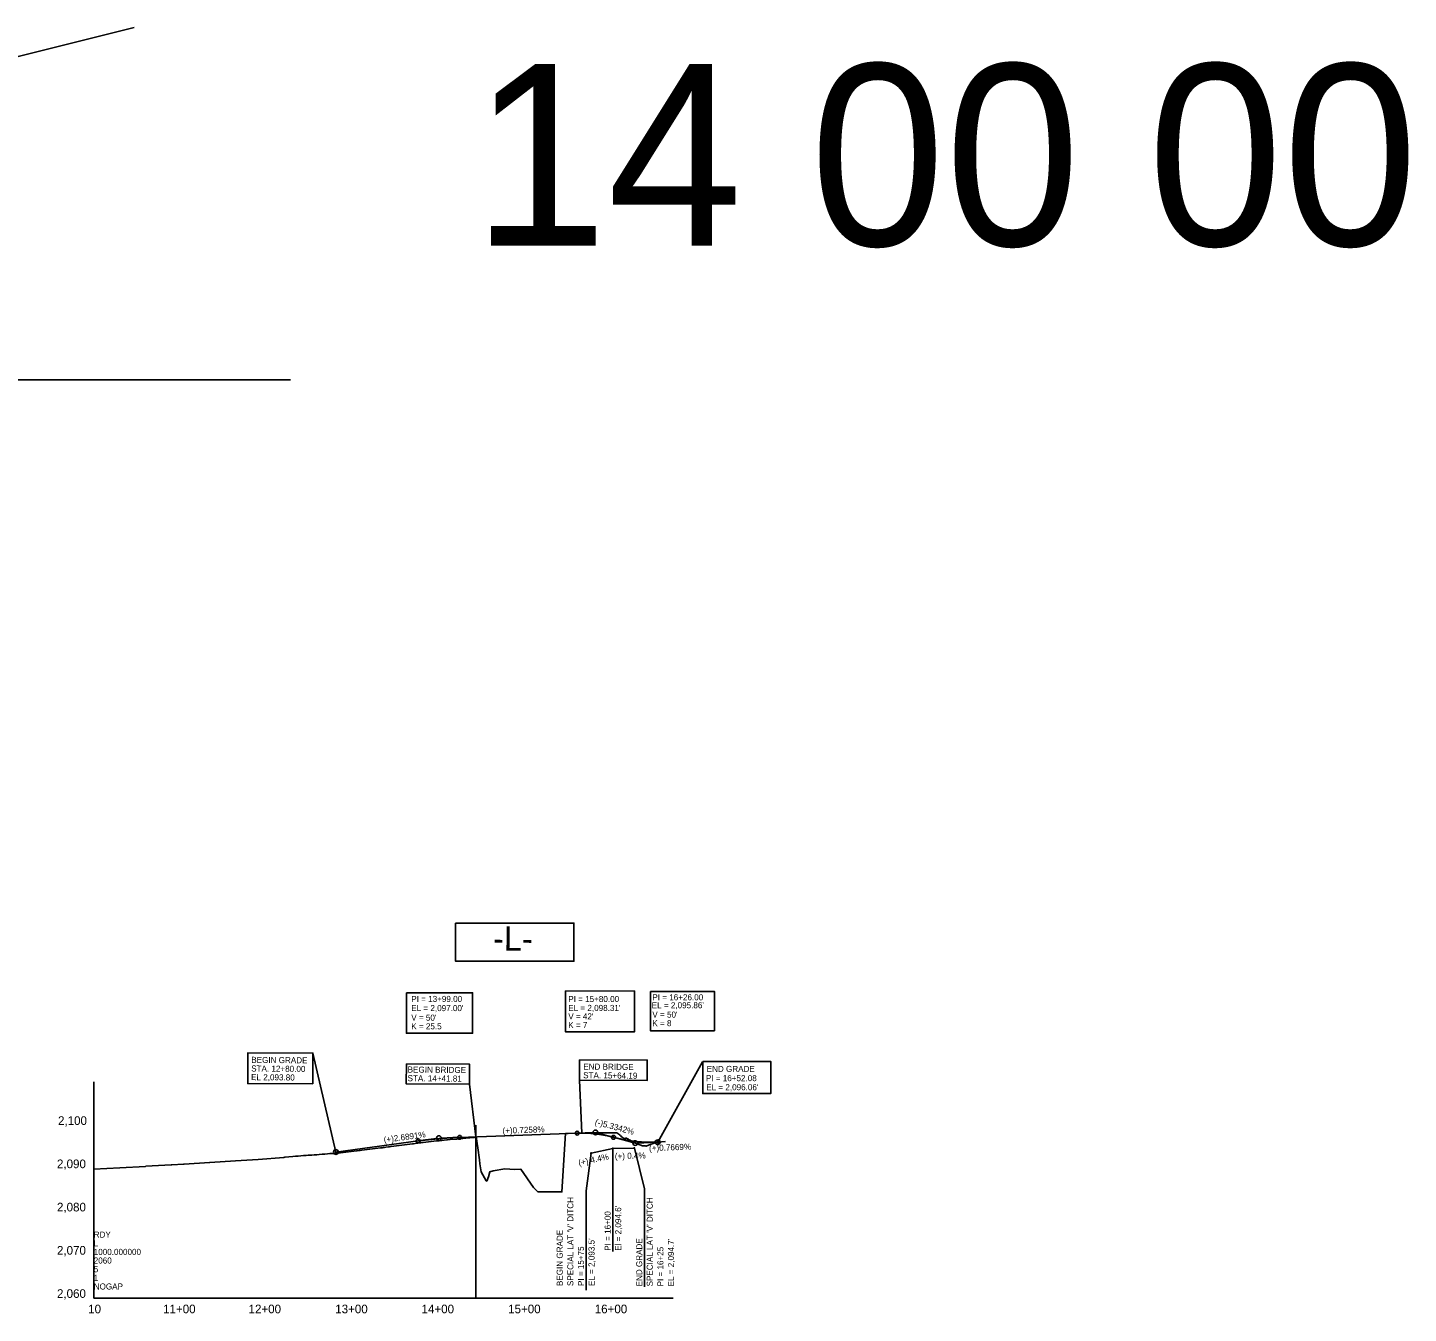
# Model space of a CAD drawing. Extents: x 1030663 to 1033857, y 654635 to 657099.
# Drawn here: x 1032261 to 1033857, y 654635 to 656121 of the extents above; entities that cross this region are included whole.
import ezdxf

# ---------------------------------------------------------------- set-up
doc = ezdxf.new("R2010")
doc.units = 0
for name, color, linetype in [('Exist Profile Cell', 7, 'Continuous'), ('Exist Vertical Profile Ground Line', 7, 'Continuous'), ('Exist Vertical Profile Horizontal Axis Label Major', 7, 'Continuous'), ('Exist Vertical Profile Vertical Axis Label', 7, 'Continuous'), ('Prop Grid Mask', 7, 'Continuous'), ('Prop Vertical Profile Curve Label', 7, 'Continuous'), ('Prop Vertical Profile Ditch Grade Right', 7, 'Continuous'), ('Prop Vertical Profile Ditch Grade Right Label', 7, 'Continuous'), ('Prop Vertical Profile Grade', 7, 'Continuous'), ('Prop Vertical Profile Grade Label', 7, 'Continuous'), ('Prop VPI Ditch Grade Right Label', 7, 'Continuous'), ('Prop VPI Label', 7, 'Continuous')]:
    doc.layers.add(name, color=color, linetype=linetype)

msp = doc.modelspace()

# ---------------------------------------------------------------- linework, layer by layer
at = {"layer": 'Exist Profile Cell'}
for q in [(1032337.1, 654902.3), (1033007.1, 654652.3), (1032337.1, 654652.3)]:
    msp.add_line((1032337.1, 654652.3), q, dxfattribs=at)
at = {"layer": 'Exist Vertical Profile Ground Line'}
msp.add_lwpolyline([(1032337.1, 654801.3), (1032367.2, 654803), (1032396.9, 654804.7), (1032397.3, 654804.8), (1032426.8, 654806.5), (1032427.3, 654806.5), (1032441, 654807.3), (1032441.5, 654807.4), (1032471, 654809.2), (1032471.3, 654809.2), (1032501.1, 654811.1), (1032527.1, 654812.7), (1032556.7, 654815.1), (1032558.2, 654815.3), (1032567.2, 654816.1), (1032570.3, 654816.3), (1032573.3, 654816.6), (1032576.4, 654816.8), (1032579.5, 654817.1), (1032582.6, 654817.3), (1032584.9, 654817.5), (1032585.6, 654817.6), (1032588.7, 654817.7), (1032589.1, 654817.7), (1032591.8, 654818), (1032594.9, 654818.2), (1032597.9, 654818.4), (1032601, 654818.7), (1032604.1, 654818.9), (1032607.2, 654819.2), (1032610.2, 654819.4), (1032611.2, 654819.5), (1032613.3, 654819.6), (1032615.5, 654819.7), (1032616.4, 654819.8), (1032619.5, 654820.1), (1032622.5, 654820.5), (1032625.6, 654820.9), (1032628.7, 654821.2), (1032631.8, 654821.6), (1032634.8, 654822), (1032637.9, 654822.4), (1032641, 654822.7), (1032641.6, 654822.8), (1032644.1, 654823.1), (1032645.1, 654823.2), (1032647.1, 654823.5), (1032650.2, 654823.8), (1032653.3, 654824.2), (1032656.4, 654824.6), (1032659.4, 654825), (1032662.5, 654825.3), (1032665.6, 654825.7), (1032668.6, 654826.1), (1032670.5, 654826.3), (1032671.7, 654826.5), (1032672.7, 654826.6), (1032673.1, 654826.6), (1032674.8, 654826.8), (1032677.9, 654827.2), (1032679.1, 654827.3), (1032680.4, 654827.5), (1032680.9, 654827.6), (1032684, 654827.9), (1032687.1, 654828.3), (1032690.2, 654828.7), (1032693.2, 654829.1), (1032696.3, 654829.5), (1032699.4, 654829.9), (1032702.5, 654830.3), (1032705.5, 654830.6), (1032706.9, 654830.8), (1032708.6, 654831), (1032711.7, 654831.4), (1032714.8, 654831.8), (1032715.4, 654831.9), (1032717.8, 654832.2), (1032720.9, 654832.6), (1032724, 654833), (1032727.1, 654833.4), (1032730.1, 654833.7), (1032733.2, 654834.1), (1032734.7, 654834.3), (1032736.3, 654834.4), (1032739.4, 654834.7), (1032742.4, 654835), (1032745.5, 654835.3), (1032746, 654835.4), (1032749, 654835.7), (1032756.7, 654836.2), (1032767.1, 654837.4), (1032776.9, 654837.9), (1032779.4, 654838.7), (1032781.1, 654826.3), (1032783.1, 654812.1), (1032783.6, 654807.7), (1032784.9, 654798.5), (1032790.8, 654788), (1032791.4, 654787.6), (1032793.3, 654792.4), (1032795.2, 654798.5), (1032798.8, 654799.5), (1032812.2, 654801.8), (1032824.1, 654801.1), (1032830.9, 654801.3), (1032845.5, 654780.1), (1032850.6, 654775.1), (1032861.2, 654775.1), (1032878.4, 654775.1), (1032882.6, 654842.6), (1032906.1, 654843.1), (1032912.5, 654843.3), (1032916.4, 654843.4), (1032917.5, 654843.4), (1032918.5, 654843.4), (1032919.5, 654843.4), (1032920.5, 654843.4), (1032921.5, 654843.4), (1032922.6, 654843.5), (1032923.6, 654843.5), (1032924.6, 654843.5), (1032925.6, 654843.5), (1032926.6, 654843.4), (1032927.7, 654843.4), (1032928.7, 654843.4), (1032929.7, 654843.4), (1032930.7, 654843.4), (1032931.7, 654843.4), (1032932.8, 654843.4), (1032933.8, 654843.4), (1032934.8, 654843.4), (1032935.8, 654843.4), (1032936.8, 654843.5), (1032937.9, 654843.5), (1032938.9, 654843.5), (1032939.2, 654843.5), (1032939.9, 654843.5), (1032940.9, 654843.5), (1032942, 654843.5), (1032943, 654842.7), (1032944, 654841.9), (1032945, 654841.1), (1032946, 654840.2), (1032947, 654839.3), (1032948.1, 654838.4), (1032949.1, 654837.5), (1032949.5, 654837), (1032950.1, 654837.1), (1032951.1, 654837.1), (1032952.1, 654837.2), (1032953.4, 654837.2), (1032954.2, 654836.7), (1032955.2, 654836.1), (1032956.2, 654835.4), (1032957.2, 654834.8), (1032958.3, 654834.1), (1032959.3, 654833.4), (1032960.3, 654832.7), (1032961.3, 654832.4), (1032962.3, 654832), (1032963.4, 654831.6), (1032964.4, 654831.3), (1032965.4, 654830.9), (1032966.4, 654830.5), (1032967.4, 654830.1), (1032968.5, 654829.7), (1032969.7, 654829.2), (1032970.5, 654828.8), (1032971.6, 654828.4), (1032972.5, 654828.3), (1032973.6, 654828.3), (1032974.6, 654828.3), (1032975.6, 654828.2), (1032976.2, 654828.2), (1032976.6, 654828.4), (1032977.6, 654828.8), (1032978.6, 654829.2), (1032979.7, 654829.6), (1032980.7, 654830), (1032981.7, 654830.3), (1032982.7, 654830.7), (1032983.7, 654831.1), (1032984.8, 654831.5), (1032986.2, 654832), (1032987.4, 654832.4), (1032987.9, 654832.6), (1032989.2, 654832.6), (1032997.9, 654833.4), (1032997.9, 654833.4)], dxfattribs=at)
at = {"layer": 'Prop Grid Mask'}
for points in [[(1032755.5, 655086), (1032892.2, 655086), (1032892.2, 655041.8), (1032755.5, 655041.8)], [(1032698.6, 655005.4), (1032775, 655005.4), (1032775, 654958.6), (1032698.6, 654958.6)], [(1032882.5, 655007.6), (1032962.3, 655007.4), (1032962.2, 654960.2), (1032882.4, 654960.4)], [(1033054.9, 654961.4), (1032980.7, 654961.5), (1032980.8, 655006.8), (1033054.9, 655006.7)], [(1032590.4, 654900.3), (1032515.2, 654900.5), (1032515.3, 654936), (1032590.5, 654935.7)], [(1032698.5, 654923.2), (1032771.4, 654923), (1032771.4, 654899.9), (1032698.4, 654900.1)], [(1032898.8, 654927.8), (1032977.1, 654927.6), (1032977.1, 654904.1), (1032898.8, 654904.2)], [(1033041.2, 654926.1), (1033119.8, 654926), (1033119.7, 654888.8), (1033041.1, 654888.9)]]:
    msp.add_lwpolyline(points, close=True, dxfattribs=at)
at = {"layer": 'Prop Vertical Profile Curve Label'}
for centre in [(1032760.1, 654838.2), (1032896.1, 654843.1), (1032938.1, 654838.3), (1032712.1, 654834.1), (1032988.1, 654832.6)]:
    msp.add_circle(centre, 2.25, dxfattribs=at)
at = {"layer": 'Prop Vertical Profile Ditch Grade Right'}
msp.add_lwpolyline([(1032912.1, 654819.8), (1032937.1, 654825.3), (1032962.1, 654825.8)], dxfattribs=at)
at = {"layer": 'Prop Vertical Profile Grade'}
for p, q in [((1032760.1, 654838.2), (1032896.1, 654843.1)), ((1032617.1, 654821.3), (1032712.1, 654834.1)), ((1032988.1, 654832.6), (1032989.2, 654832.6))]:
    msp.add_line(p, q, dxfattribs=at)
for points in [[(1032896.1, 654843.1), (1032897, 654843.2), (1032897.8, 654843.2), (1032898.7, 654843.2), (1032899.5, 654843.2), (1032900.3, 654843.2), (1032901.2, 654843.2), (1032902, 654843.2), (1032902.9, 654843.2), (1032903.7, 654843.2), (1032904.5, 654843.2), (1032905.4, 654843.2), (1032906.2, 654843.1), (1032907.1, 654843.1), (1032907.9, 654843.1), (1032908.7, 654843), (1032909.6, 654843), (1032910.4, 654842.9), (1032911.3, 654842.9), (1032912.1, 654842.8), (1032912.9, 654842.7), (1032913.8, 654842.7), (1032914.6, 654842.6), (1032915.5, 654842.5), (1032916.3, 654842.4), (1032917.1, 654842.3), (1032918, 654842.2), (1032918.8, 654842.1), (1032919.7, 654842), (1032920.5, 654841.9), (1032921.3, 654841.8), (1032922.2, 654841.6), (1032923, 654841.5), (1032923.9, 654841.4), (1032924.7, 654841.2), (1032925.5, 654841.1), (1032926.4, 654840.9), (1032927.2, 654840.8), (1032928.1, 654840.6), (1032928.9, 654840.5), (1032929.7, 654840.3), (1032930.6, 654840.1), (1032931.4, 654839.9), (1032932.3, 654839.7), (1032933.1, 654839.5), (1032933.9, 654839.4), (1032934.8, 654839.1), (1032935.6, 654838.9), (1032936.5, 654838.7), (1032937.3, 654838.5), (1032938.1, 654838.3)], [(1032712.1, 654834.1), (1032713.1, 654834.2), (1032714.1, 654834.4), (1032715, 654834.5), (1032716, 654834.6), (1032716.9, 654834.7), (1032717.9, 654834.8), (1032718.9, 654835), (1032719.8, 654835.1), (1032720.8, 654835.2), (1032721.7, 654835.3), (1032722.7, 654835.4), (1032723.7, 654835.5), (1032724.6, 654835.6), (1032725.6, 654835.7), (1032726.5, 654835.8), (1032727.5, 654835.9), (1032728.5, 654836), (1032729.4, 654836.1), (1032730.4, 654836.2), (1032731.3, 654836.3), (1032732.3, 654836.4), (1032733.3, 654836.5), (1032734.2, 654836.6), (1032735.2, 654836.7), (1032736.1, 654836.7), (1032737.1, 654836.8), (1032738.1, 654836.9), (1032739, 654837), (1032740, 654837.1), (1032740.9, 654837.1), (1032741.9, 654837.2), (1032742.9, 654837.3), (1032743.8, 654837.3), (1032744.8, 654837.4), (1032745.7, 654837.5), (1032746.7, 654837.5), (1032747.7, 654837.6), (1032748.6, 654837.6), (1032749.6, 654837.7), (1032750.5, 654837.8), (1032751.5, 654837.8), (1032752.5, 654837.9), (1032753.4, 654837.9), (1032754.4, 654838), (1032755.3, 654838), (1032756.3, 654838), (1032757.3, 654838.1), (1032758.2, 654838.1), (1032759.2, 654838.2), (1032760.1, 654838.2)], [(1032938.1, 654838.3), (1032939.1, 654838), (1032940.1, 654837.8), (1032941.1, 654837.5), (1032942.1, 654837.3), (1032943.1, 654837), (1032944.1, 654836.8), (1032945.1, 654836.6), (1032946.1, 654836.4), (1032947.1, 654836.1), (1032948.1, 654835.9), (1032949.1, 654835.7), (1032950.1, 654835.5), (1032951.1, 654835.3), (1032952.1, 654835.2), (1032953.1, 654835), (1032954.1, 654834.8), (1032955.1, 654834.6), (1032956.1, 654834.5), (1032957.1, 654834.3), (1032958.1, 654834.2), (1032959.1, 654834), (1032960.1, 654833.9), (1032961.1, 654833.8), (1032962.1, 654833.6), (1032963.1, 654833.5), (1032964.1, 654833.4), (1032965.1, 654833.3), (1032966.1, 654833.2), (1032967.1, 654833.1), (1032968.1, 654833), (1032969.1, 654833), (1032970.1, 654832.9), (1032971.1, 654832.8), (1032972.1, 654832.7), (1032973.1, 654832.7), (1032974.1, 654832.6), (1032975.1, 654832.6), (1032976.1, 654832.6), (1032977.1, 654832.5), (1032978.1, 654832.5), (1032979.1, 654832.5), (1032980.1, 654832.5), (1032981.1, 654832.5), (1032982.1, 654832.5), (1032983.1, 654832.5), (1032984.1, 654832.5), (1032985.1, 654832.5), (1032986.1, 654832.5), (1032987.1, 654832.5), (1032988.1, 654832.6)]]:
    msp.add_spline(points, degree=3, dxfattribs=at)
at = {"layer": 'Prop Vertical Profile Grade Label'}
for p, q in [((1030750.5, 655714.1), (1032384, 656121.4)), ((1030750.5, 655714.1), (1032564.7, 655714.1)), ((1032617.1, 654821.3), (1032590.5, 654935.7)), ((1032989.2, 654832.6), (1033040.7, 654925.7)), ((1032901.3, 654843.2), (1032898.8, 654904.2)), ((1032771.4, 654899.9), (1032779, 654838.9)), ((1032779, 654652.3), (1032779, 654852.3))]:
    msp.add_line(p, q, dxfattribs=at)
at = {"layer": 'Prop VPI Ditch Grade Right Label'}
for p, q in [((1032937.1, 654706.2), (1032937.1, 654825.3)), ((1032973.9, 654778.8), (1032962.1, 654825.8)), ((1032906.3, 654776.3), (1032912.1, 654819.8)), ((1032973.9, 654665.5), (1032973.9, 654778.8)), ((1032906.3, 654661.7), (1032906.3, 654776.3))]:
    msp.add_line(p, q, dxfattribs=at)
for centre in [(1032937.1, 654825.3), (1032962.1, 654825.8), (1032912.1, 654819.8)]:
    msp.add_circle(centre, 0.5, dxfattribs=at)
at = {"layer": 'Prop VPI Label'}
for p, q in [((1032896.1, 654843.1), (1032914.4, 654843.8)), ((1032938.1, 654838.3), (1032919.8, 654843.2)), ((1032712.1, 654834.1), (1032733.4, 654837)), ((1032760.1, 654838.2), (1032738.9, 654837.4)), ((1032938.1, 654838.3), (1032960.5, 654832.3)), ((1032988.1, 654832.6), (1032965.9, 654831.7))]:
    msp.add_line(p, q, dxfattribs=at)
for centre in [(1032917.1, 654843.9), (1032736.1, 654837.3), (1032963.1, 654831.6), (1032989.2, 654832.6), (1032617.1, 654821.3)]:
    msp.add_circle(centre, 2.75, dxfattribs=at)

# ---------------------------------------------------------------- texts
at = {"layer": 'Exist Profile Cell'}
for s, p in [('RDY', (1032337.1, 654722.3)), ('L', (1032337.1, 654712.3)), ('2060', (1032337.1, 654692.3)), ('1000.000000', (1032337.1, 654702.3)), ('5', (1032337.1, 654682.3)), ('1', (1032337.1, 654672.3)), ('NOGAP', (1032337.1, 654662.3))]:
    msp.add_text(s, height=7, dxfattribs=at).set_placement(p)
at = {"layer": 'Exist Vertical Profile Horizontal Axis Label Major'}
for s, p in [('10', (1032330.7, 654634.8)), ('11+00', (1032417.3, 654634.8)), ('12+00', (1032516.1, 654634.8)), ('13+00', (1032616.3, 654634.8)), ('14+00', (1032716.1, 654634.8)), ('15+00', (1032816.2, 654634.8)), ('16+00', (1032916.3, 654634.8))]:
    msp.add_text(s, height=10, dxfattribs=at).set_placement(p)
at = {"layer": 'Exist Vertical Profile Vertical Axis Label'}
for s, p in [('2,100', (1032295.8, 654852.6)), ('2,090', (1032294.6, 654802.6)), ('2,080', (1032294.6, 654752.6)), ('2,070', (1032294.6, 654702.6)), ('2,060', (1032294.6, 654652.6))]:
    msp.add_text(s, height=10, dxfattribs=at).set_placement(p)
at = {"layer": 'Prop Vertical Profile Ditch Grade Right Label'}
for s, rotation, p in [('(+) 4.4%', 12.4074, (1032898.2, 654805.2)), ('(+) 0.4%', 1.1458, (1032939.6, 654813.1))]:
    msp.add_text(s, height=7, rotation=rotation, dxfattribs=at).set_placement(p)
at = {"layer": 'Prop Vertical Profile Grade Label'}
msp.add_text('14 00 00', height=210, dxfattribs=at).set_placement((1032774.8, 655869.3))
for s, rotation, p in [('STA. 12+80.00', 359.4999, (1032519.1, 654914.4)), ('BEGIN GRADE', 359.4999, (1032519.2, 654924.4)), ('BEGIN BRIDGE', 359.4999, (1032700, 654913.2)), ('END BRIDGE', 359.4999, (1032903, 654916.6)), ('EL 2,093.80', 359.4999, (1032519, 654904.4)), ('STA. 14+41.81', 359.4999, (1032699.9, 654903.2)), ('STA. 15+64.19', 359.4999, (1032902.9, 654906.6)), ('(-)5.3342%', 345.0537, (1032916, 654853)), ('(+)2.6891%', 7.6577, (1032672.9, 654831.9)), ('(+)0.7258%', 2.0784, (1032809.8, 654842.4)), ('(+)0.7669%', 2.2048, (1032979.2, 654822.2))]:
    msp.add_text(s, height=7, rotation=rotation, dxfattribs=at).set_placement(p)
at = {"layer": 'Prop VPI Ditch Grade Right Label'}
for s, p in [("SPECIAL LAT 'V' DITCH", (1032891.6, 654666.3)), ("SPECIAL LAT 'V' DITCH", (1032983.4, 654665.9)), ('PI = 16+00', (1032934.7, 654707.1)), ("El = 2,094.6'", (1032946.9, 654707.1)), ('BEGIN GRADE', (1032879.3, 654666.3)), ("EL = 2,093.5'", (1032916.1, 654666.3)), ('END GRADE', (1032971.2, 654665.9)), ("EL = 2,094.7'", (1033007.9, 654665.9)), ('PI = 15+75', (1032903.8, 654666.3)), ('PI = 16+25', (1032995.7, 654665.9))]:
    msp.add_text(s, height=7, rotation=90, dxfattribs=at).set_placement(p)
at = {"layer": 'Prop VPI Label'}
msp.add_text('-L-', height=28, rotation=359.4999, dxfattribs=at).set_placement((1032798.7, 655054.3))
for s, p in [('PI = 13+99.00', (1032704.2, 654994.8)), ('PI = 15+80.00', (1032885.7, 654994.7)), ('PI = 16+26.00', (1032982.9, 654996.7)), ("EL = 2,097.00'", (1032704.2, 654984.2)), ("EL = 2,098.31'", (1032885.7, 654984.4)), ("EL = 2,095.86'", (1032982.2, 654987.5)), ("V = 50'", (1032704.2, 654973.2)), ('K = 25.5', (1032704.2, 654963.2)), ("V = 42'", (1032885.7, 654974.7)), ('K = 7', (1032885.7, 654964.6)), ("V = 50'", (1032982.9, 654976.7)), ('K = 8', (1032982.9, 654966.8)), ('END GRADE', (1033045.7, 654913.9)), ('PI = 16+52.08', (1033044.8, 654903.2)), ("EL = 2,096.06'", (1033045.2, 654892.7))]:
    msp.add_text(s, height=7, dxfattribs=at).set_placement(p)

doc.saveas('drawing.dxf')
